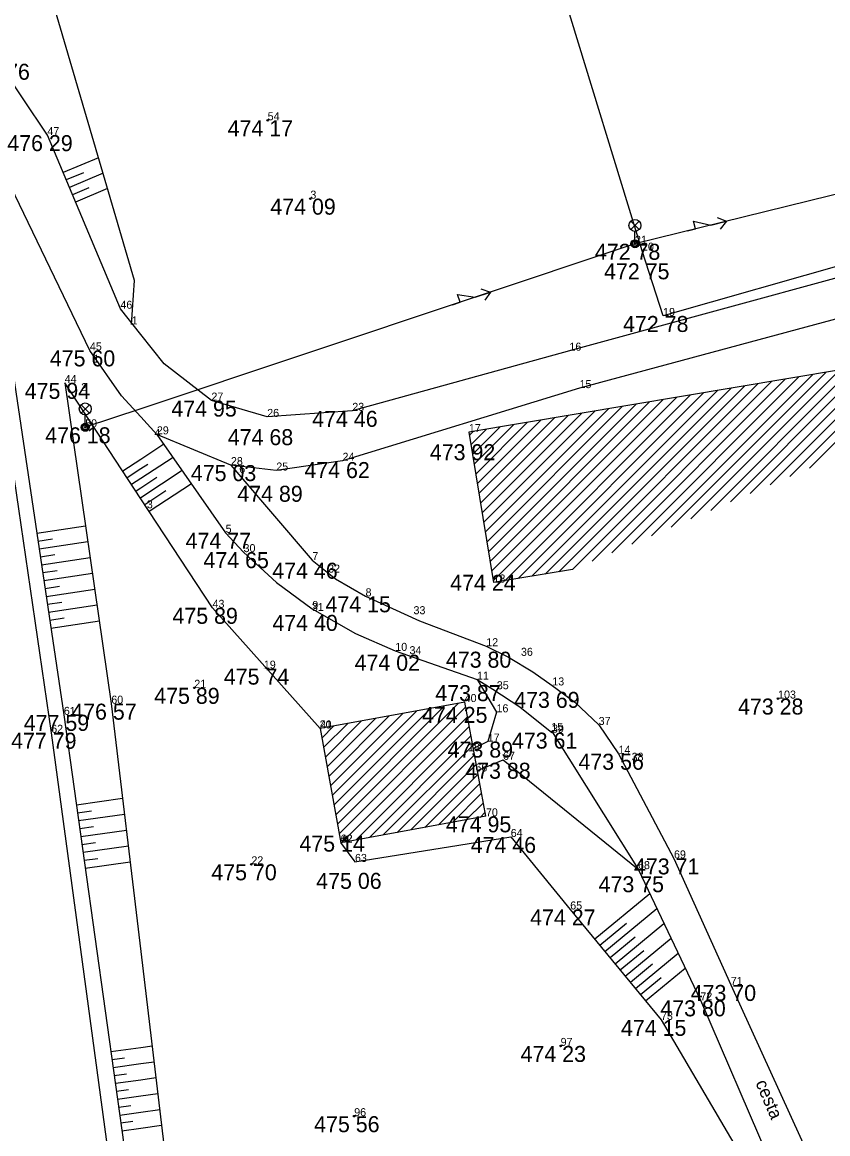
# Model space of a CAD drawing. Extents: x -559180 to -551373, y -1076947 to -1072071.
# Drawn here: x -553757.4 to -553707, y -1075865 to -1075795.6 of the extents above; entities that cross this region are included whole.
import ezdxf

# ---------------------------------------------------------------- set-up
doc = ezdxf.new("R2010")
doc.units = 0
for name, color, linetype in [('12_PLOTY', 7, 'Continuous'), ('14_BUDOVY', 7, 'Continuous'), ('17_KOMUNIKACE', 7, 'Continuous'), ('1_VODA_ZN', 7, 'Continuous'), ('20_EL_ZN', 7, 'Continuous'), ('26_SRAFY', 7, 'Continuous'), ('27_HRANA_PATA', 7, 'Continuous'), ('32', 7, 'Continuous'), ('3_BODY', 7, 'Continuous'), ('52_POPIS_UCELOVY', 7, 'Continuous'), ('6_VYSKY', 7, 'Continuous'), ('NNnadzemní', 7, 'Continuous')]:
    doc.layers.add(name, color=color, linetype=linetype)

# ---------------------------------------------------------------- blocks, each defined once
blk = doc.blocks.new('POINT_DISPLAY')
blk.add_line((0, 0), (0, 0))
blk = doc.blocks.new('SLB')
at = {"layer": '20_EL_ZN'}
for radius in [0.25, 0.158, 0.05]:
    blk.add_circle((0, 0), radius, dxfattribs=at)
blk = doc.blocks.new('LA')
at = {"layer": '20_EL_ZN'}
for p, q in [((-0.265, 1.415), (0.265, 0.885)), ((-0.265, 0.885), (0.265, 1.415)), ((0, 0), (0, 0.775))]:
    blk.add_line(p, q, dxfattribs=at)
for centre, radius in [((0, 1.15), 0.375), ((0, 0), 0.19), ((0, 0), 0.05)]:
    blk.add_circle(centre, radius, dxfattribs=at)
blk = doc.blocks.new('SLDP')
at = {"layer": '20_EL_ZN'}
for radius in [0.25, 0.158, 0.05]:
    blk.add_circle((0, 0), radius, dxfattribs=at)
blk = doc.blocks.new('T')
at = {"layer": '6_VYSKY'}
blk.add_circle((0, 0), 0.05, dxfattribs=at)
blk = doc.blocks.new('ELNN')
at = {"layer": '20_EL_ZN'}
for p, q in [((0, 0), (0.5, 0)), ((0.5, 0), (0.5, 0.5)), ((0.5, 0.5), (1.5, 0)), ((1.5, 0), (2.5, 0))]:
    blk.add_line(p, q, dxfattribs=at)
blk.add_lwpolyline([(2, 0.375), (2.5, 0), (2, -0.375)], dxfattribs=at)

msp = doc.modelspace()

# ---------------------------------------------------------------- linework, layer by layer
at = {"layer": '12_PLOTY'}
for p, q in [((-553718.66, -1075809.85), (-553725.883, -1075786.26)), ((-553717.34, -1075813.93), (-553718.66, -1075809.85)), ((-553703.74, -1075810.04), (-553717.34, -1075813.93))]:
    msp.add_line(p, q, dxfattribs=at)
at = {"layer": '14_BUDOVY'}
for p, q in [((-553706.13, -1075817.27), (-553729.49, -1075821.19)), ((-553729.49, -1075821.19), (-553727.95, -1075830.59)), ((-553723.016, -1075829.782), (-553727.95, -1075830.59)), ((-553729.75, -1075838.06), (-553738.79, -1075839.71)), ((-553728.42, -1075845.2), (-553729.75, -1075838.06)), ((-553738.79, -1075839.71), (-553737.5, -1075846.85)), ((-553728.42, -1075845.2), (-553737.5, -1075846.85))]:
    msp.add_line(p, q, dxfattribs=at)
at = {"layer": '17_KOMUNIKACE'}
for p, q in [((-553755.85, -1075802.63), (-553759.5, -1075797.19)), ((-553761.18, -1075801.95), (-553755.61, -1075839.98)), ((-553751.28, -1075813.48), (-553755.85, -1075802.63)), ((-553753.19, -1075816.08), (-553759.1, -1075803.86)), ((-553700, -1075809.79), (-553723.2, -1075816.1)), ((-553699.17, -1075812.14), (-553722.57, -1075818.44)), ((-553750, -1075815.096), (-553751.28, -1075813.48)), ((-553723.2, -1075816.1), (-553736.78, -1075819.86)), ((-553722.57, -1075818.44), (-553737.39, -1075822.98)), ((-553742.1, -1075820.24), (-553745.59, -1075819.22)), ((-553736.78, -1075819.86), (-553742.1, -1075820.24)), ((-553749, -1075821.33), (-553750, -1075820.236)), ((-553744.37, -1075823.25), (-553749, -1075821.33)), ((-553741.53, -1075823.59), (-553744.37, -1075823.25)), ((-553744.37, -1075823.25), (-553739.28, -1075829.19)), ((-553737.39, -1075822.98), (-553741.53, -1075823.59)), ((-553734.09, -1075834.86), (-553728.98, -1075836.66)), ((-553755.61, -1075839.98), (-553751.45, -1075870.69)), ((-553724.33, -1075839.86), (-553718.91, -1075848.5)), ((-553720.13, -1075841.29), (-553716.66, -1075847.83)), ((-553716.66, -1075847.83), (-553713.11, -1075855.74)), ((-553718.91, -1075848.5), (-553715.01, -1075856.7)), ((-553713.11, -1075855.74), (-553705.39, -1075872.58)), ((-553715.01, -1075856.7), (-553707.73, -1075873.54))]:
    msp.add_line(p, q, dxfattribs=at)
for points in [[(-553745.59, -1075819.22), (-553748.554, -1075816.921), (-553750, -1075815.096)], [(-553750, -1075820.236), (-553751.209, -1075818.914), (-553753.19, -1075816.08)], [(-553749, -1075821.33), (-553744.7, -1075827.48), (-553743.58, -1075828.69)], [(-553743.58, -1075828.69), (-553741.509, -1075830.583), (-553739.28, -1075832.24)], [(-553739.28, -1075829.19), (-553737.839, -1075830.365), (-553735.95, -1075831.45)], [(-553735.95, -1075831.45), (-553732.581, -1075832.974), (-553728.4, -1075834.57)], [(-553739.28, -1075832.24), (-553736.572, -1075833.772), (-553734.09, -1075834.86)], [(-553728.4, -1075834.57), (-553727.016, -1075835.244), (-553725.487, -1075836.162), (-553724.27, -1075837.02)], [(-553728.98, -1075836.66), (-553727.999, -1075837.255), (-553726.295, -1075838.348), (-553724.29, -1075839.97)], [(-553724.27, -1075837.02), (-553722.852, -1075838.074), (-553721.37, -1075839.49), (-553720.13, -1075841.29)]]:
    msp.add_lwpolyline(points, dxfattribs=at)
at = {"layer": '26_SRAFY'}
for p, q in [((-553752.653, -1075804.041), (-553754.864, -1075804.972)), ((-553753.59, -1075804.978), (-553754.67, -1075805.433)), ((-553752.369, -1075805.006), (-553754.475, -1075805.893)), ((-553753.255, -1075805.922), (-553754.281, -1075806.354)), ((-553752.086, -1075805.972), (-553754.087, -1075806.815)), ((-553748.565, -1075821.952), (-553750, -1075822.895)), ((-553750, -1075822.895), (-553751.128, -1075823.637)), ((-553747.992, -1075822.772), (-553750, -1075824.092)), ((-553749.566, -1075823.208), (-553750, -1075823.494)), ((-553750, -1075823.494), (-553750.853, -1075824.055)), ((-553750, -1075824.092), (-553750.579, -1075824.472)), ((-553747.418, -1075823.592), (-553750, -1075825.289)), ((-553749.004, -1075824.036), (-553750, -1075824.69)), ((-553750, -1075824.69), (-553750.304, -1075824.89)), ((-553746.845, -1075824.412), (-553749.48, -1075826.144)), ((-553750, -1075825.289), (-553750.029, -1075825.308)), ((-553748.443, -1075824.864), (-553749.755, -1075825.726)), ((-553753.46, -1075827.066), (-553756.51, -1075827.52)), ((-553755.522, -1075827.879), (-553756.436, -1075828.015)), ((-553753.316, -1075828.056), (-553756.362, -1075828.51)), ((-553755.375, -1075828.868), (-553756.289, -1075829.004)), ((-553753.173, -1075829.045), (-553756.215, -1075829.499)), ((-553755.229, -1075829.857), (-553756.141, -1075829.993)), ((-553753.029, -1075830.035), (-553756.068, -1075830.488)), ((-553755.083, -1075830.846), (-553755.994, -1075830.982)), ((-553752.886, -1075831.025), (-553755.92, -1075831.477)), ((-553754.937, -1075831.836), (-553755.847, -1075831.971)), ((-553752.742, -1075832.014), (-553755.773, -1075832.466)), ((-553754.79, -1075832.825), (-553755.699, -1075832.96)), ((-553752.598, -1075833.004), (-553755.625, -1075833.455)), ((-553751.141, -1075844.095), (-553754.032, -1075844.499)), ((-553753.098, -1075844.873), (-553753.962, -1075844.994)), ((-553751.022, -1075845.088), (-553753.893, -1075845.489)), ((-553752.966, -1075845.865), (-553753.824, -1075845.985)), ((-553750.904, -1075846.081), (-553753.755, -1075846.48)), ((-553752.833, -1075846.856), (-553753.685, -1075846.975)), ((-553750.785, -1075847.074), (-553753.616, -1075847.47)), ((-553752.701, -1075847.847), (-553753.547, -1075847.965)), ((-553750.667, -1075848.068), (-553753.478, -1075848.461)), ((-553718.171, -1075850.053), (-553721.614, -1075852.886)), ((-553717.729, -1075850.984), (-553720.978, -1075853.659)), ((-553719.623, -1075851.895), (-553721.296, -1075853.273)), ((-553717.286, -1075851.915), (-553720.342, -1075854.431)), ((-553719.084, -1075852.747), (-553720.66, -1075854.045)), ((-553716.843, -1075852.845), (-553719.707, -1075855.203)), ((-553718.545, -1075853.598), (-553720.025, -1075854.817)), ((-553716.401, -1075853.776), (-553719.071, -1075855.975)), ((-553718.006, -1075854.45), (-553719.389, -1075855.589)), ((-553717.466, -1075855.301), (-553718.754, -1075856.361)), ((-553715.958, -1075854.707), (-553718.436, -1075856.747)), ((-553750, -1075859.665), (-553751.875, -1075859.927)), ((-553749.294, -1075859.566), (-553750, -1075859.665)), ((-553751.034, -1075860.314), (-553751.806, -1075860.422)), ((-553750, -1075860.674), (-553751.736, -1075860.917)), ((-553749.175, -1075860.559), (-553750, -1075860.674)), ((-553750.902, -1075861.305), (-553751.667, -1075861.412)), ((-553749.057, -1075861.552), (-553750, -1075861.684)), ((-553750, -1075861.684), (-553751.598, -1075861.908)), ((-553750.769, -1075862.297), (-553751.529, -1075862.403)), ((-553750, -1075862.694), (-553751.459, -1075862.898)), ((-553748.938, -1075862.545), (-553750, -1075862.694)), ((-553750.637, -1075863.288), (-553751.39, -1075863.393)), ((-553750, -1075863.704), (-553751.321, -1075863.888)), ((-553748.82, -1075863.539), (-553750, -1075863.704)), ((-553750.504, -1075864.279), (-553751.252, -1075864.383)), ((-553750, -1075864.714), (-553751.182, -1075864.879)), ((-553748.701, -1075864.532), (-553750, -1075864.714))]:
    msp.add_line(p, q, dxfattribs=at)
at = {"layer": '27_HRANA_PATA'}
for p, q in [((-553750.4, -1075811.72), (-553755.78, -1075793.38)), ((-553759.66, -1075806.38), (-553754.82, -1075838.86)), ((-553750.58, -1075814.46), (-553750.4, -1075811.72)), ((-553750, -1075825.353), (-553754.76, -1075818.11)), ((-553754.76, -1075818.11), (-553751.85, -1075838.16)), ((-553745.52, -1075832.17), (-553750, -1075825.353)), ((-553738.79, -1075839.71), (-553745.52, -1075832.17)), ((-553728.98, -1075836.66), (-553727.76, -1075838.7)), ((-553751.85, -1075838.16), (-553750, -1075853.654)), ((-553727.76, -1075838.7), (-553728.31, -1075840.53)), ((-553754.82, -1075838.86), (-553750.5, -1075869.76)), ((-553728.31, -1075840.53), (-553729.208, -1075840.968)), ((-553728.952, -1075842.346), (-553727.35, -1075841.67)), ((-553727.35, -1075841.67), (-553718.91, -1075848.5)), ((-553737.51, -1075846.84), (-553736.61, -1075848.05)), ((-553736.61, -1075848.05), (-553726.87, -1075846.49)), ((-553726.87, -1075846.49), (-553723.15, -1075851.02)), ((-553723.15, -1075851.02), (-553717.47, -1075857.92)), ((-553750, -1075853.654), (-553748.25, -1075868.31)), ((-553717.47, -1075857.92), (-553708.16, -1075873.68))]:
    msp.add_line(p, q, dxfattribs=at)
at = {"layer": '32'}
for p, q in [((-553720.544, -1075828.724), (-553709.687, -1075817.867)), ((-553719.307, -1075828.195), (-553708.837, -1075817.724)), ((-553718.071, -1075827.666), (-553707.987, -1075817.582)), ((-553716.835, -1075827.137), (-553707.138, -1075817.439)), ((-553715.599, -1075826.608), (-553706.288, -1075817.296)), ((-553714.363, -1075826.078), (-553706.047, -1075817.763)), ((-553725.553, -1075830.197), (-553713.935, -1075818.58)), ((-553724.707, -1075830.059), (-553713.085, -1075818.437)), ((-553723.862, -1075829.92), (-553712.236, -1075818.295)), ((-553723.016, -1075829.782), (-553711.386, -1075818.152)), ((-553721.78, -1075829.253), (-553710.536, -1075818.009)), ((-553713.127, -1075825.549), (-553705.946, -1075818.369)), ((-553728.066, -1075829.882), (-553717.334, -1075819.15)), ((-553727.966, -1075830.49), (-553716.484, -1075819.008)), ((-553727.244, -1075830.474), (-553715.634, -1075818.865)), ((-553726.398, -1075830.336), (-553714.785, -1075818.722)), ((-553711.89, -1075825.02), (-553705.844, -1075818.974)), ((-553728.564, -1075826.844), (-553721.582, -1075819.863)), ((-553728.464, -1075827.452), (-553720.733, -1075819.72)), ((-553728.365, -1075828.06), (-553719.883, -1075819.578)), ((-553728.265, -1075828.667), (-553719.033, -1075819.435)), ((-553728.165, -1075829.275), (-553718.184, -1075819.293)), ((-553710.654, -1075824.491), (-553705.743, -1075819.58)), ((-553729.061, -1075823.807), (-553725.831, -1075820.576)), ((-553728.962, -1075824.414), (-553724.981, -1075820.433)), ((-553728.862, -1075825.022), (-553724.131, -1075820.291)), ((-553728.763, -1075825.629), (-553723.282, -1075820.148)), ((-553728.663, -1075826.237), (-553722.432, -1075820.006)), ((-553709.418, -1075823.962), (-553705.641, -1075820.185)), ((-553729.459, -1075821.376), (-553729.23, -1075821.146)), ((-553729.36, -1075821.984), (-553728.38, -1075821.004)), ((-553729.26, -1075822.591), (-553727.53, -1075820.861)), ((-553729.161, -1075823.199), (-553726.68, -1075820.719)), ((-553708.182, -1075823.433), (-553705.54, -1075820.791)), ((-553738.033, -1075843.902), (-553732.735, -1075838.605)), ((-553737.924, -1075844.501), (-553731.87, -1075838.447)), ((-553737.816, -1075845.1), (-553731.005, -1075838.289)), ((-553737.708, -1075845.699), (-553730.14, -1075838.131)), ((-553737.6, -1075846.298), (-553729.689, -1075838.387)), ((-553738.574, -1075840.908), (-553737.06, -1075839.394)), ((-553738.465, -1075841.507), (-553736.195, -1075839.236)), ((-553738.357, -1075842.106), (-553735.33, -1075839.078)), ((-553738.249, -1075842.705), (-553734.465, -1075838.921)), ((-553738.141, -1075843.303), (-553733.6, -1075838.763)), ((-553737.432, -1075846.838), (-553729.578, -1075838.983)), ((-553738.682, -1075840.309), (-553737.925, -1075839.552)), ((-553736.568, -1075846.681), (-553729.467, -1075839.579)), ((-553735.704, -1075846.524), (-553729.356, -1075840.175)), ((-553734.84, -1075846.367), (-553729.245, -1075840.772)), ((-553733.976, -1075846.21), (-553729.134, -1075841.368)), ((-553733.112, -1075846.053), (-553729.023, -1075841.964)), ((-553732.248, -1075845.896), (-553728.912, -1075842.56)), ((-553731.383, -1075845.739), (-553728.801, -1075843.156)), ((-553730.519, -1075845.581), (-553728.69, -1075843.752)), ((-553729.655, -1075845.424), (-553728.579, -1075844.348)), ((-553728.791, -1075845.267), (-553728.468, -1075844.944))]:
    msp.add_line(p, q, dxfattribs=at)
at = {"layer": 'NNnadzemní'}
for p, q in [((-553681.605, -1075800.205), (-553719.1, -1075809.42)), ((-553719.1, -1075809.42), (-553750, -1075819.729)), ((-553750, -1075819.729), (-553753.48, -1075820.89))]:
    msp.add_line(p, q, dxfattribs=at)

# ---------------------------------------------------------------- block references
at = {"layer": '1_VODA_ZN'}
for p in [(-553742.07, -1075801.7), (-553755.85, -1075802.63), (-553739.4, -1075806.6), (-553719.1, -1075809.42), (-553718.66, -1075809.85), (-553750.4, -1075811.72), (-553751.28, -1075813.48), (-553717.34, -1075813.93), (-553750.58, -1075814.46), (-553753.19, -1075816.08), (-553723.2, -1075816.1), (-553754.76, -1075818.11), (-553722.57, -1075818.44), (-553745.59, -1075819.22), (-553736.78, -1075819.86), (-553742.1, -1075820.24), (-553753.48, -1075820.89), (-553749, -1075821.33), (-553729.49, -1075821.19), (-553749.16, -1075821.49), (-553744.37, -1075823.25), (-553737.39, -1075822.98), (-553743.85, -1075823.74), (-553741.53, -1075823.59), (-553749.63, -1075825.95), (-553744.7, -1075827.48), (-553743.58, -1075828.69), (-553739.28, -1075829.19), (-553738.29, -1075829.97), (-553727.95, -1075830.59), (-553735.95, -1075831.45), (-553745.52, -1075832.17), (-553739.31, -1075832.37), (-553739.28, -1075832.24), (-553732.95, -1075832.57), (-553734.09, -1075834.86), (-553733.2, -1075835.07), (-553728.4, -1075834.57), (-553726.23, -1075835.17), (-553742.31, -1075835.97), (-553746.66, -1075837.17), (-553728.98, -1075836.66), (-553727.74, -1075837.26), (-553724.27, -1075837.02), (-553710.15, -1075837.84), (-553751.85, -1075838.16), (-553729.75, -1075838.06), (-553727.76, -1075838.7), (-553754.82, -1075838.86), (-553755.61, -1075839.98), (-553738.82, -1075839.71), (-553738.79, -1075839.71), (-553724.33, -1075839.86), (-553724.29, -1075839.97), (-553721.37, -1075839.49), (-553728.31, -1075840.53), (-553729.54, -1075841.13), (-553720.13, -1075841.29), (-553727.35, -1075841.67), (-553719.31, -1075841.73), (-553729.08, -1075842.4), (-553728.42, -1075845.2), (-553737.51, -1075846.84), (-553737.5, -1075846.85), (-553726.87, -1075846.49), (-553743.09, -1075848.2), (-553736.61, -1075848.05), (-553716.66, -1075847.83), (-553718.91, -1075848.5), (-553723.15, -1075851.02), (-553713.11, -1075855.74), (-553715.01, -1075856.7), (-553717.47, -1075857.92), (-553723.75, -1075859.55), (-553736.66, -1075863.94)]:
    msp.add_blockref('POINT_DISPLAY', p, dxfattribs=at)
at = {"layer": '20_EL_ZN'}
for name, p in [('LA', (-553719.1, -1075809.42)), ('SLDP', (-553719.1, -1075809.42)), ('LA', (-553753.48, -1075820.89)), ('SLB', (-553753.48, -1075820.89))]:
    msp.add_blockref(name, p, dxfattribs=at)
for p, xscale, yscale, rotation in [((-553715.807, -1075808.611), 0.999999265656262, 0.999999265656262, 13.80781763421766), ((-553730.512, -1075813.227), 1.000000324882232, 1.000000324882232, 18.45005123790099)]:
    msp.add_blockref('ELNN', p, dxfattribs=dict(at, xscale=xscale, yscale=yscale, rotation=rotation))
at = {"layer": '32'}
for p in [(-553723.016, -1075829.782), (-553738.79, -1075839.71)]:
    msp.add_blockref('POINT_DISPLAY', p, dxfattribs=at)
at = {"layer": '6_VYSKY'}
for p in [(-553742.07, -1075801.7), (-553742.07, -1075801.7), (-553739.4, -1075806.6), (-553739.4, -1075806.6), (-553746.66, -1075837.17), (-553746.66, -1075837.17), (-553710.15, -1075837.84), (-553710.15, -1075837.84), (-553743.09, -1075848.2), (-553743.09, -1075848.2), (-553723.75, -1075859.55), (-553723.75, -1075859.55), (-553736.66, -1075863.94), (-553736.66, -1075863.94)]:
    msp.add_blockref('T', p, dxfattribs=at)

# ---------------------------------------------------------------- texts
at = {"layer": '3_BODY'}
for s, p in [('54', (-553742.07, -1075801.7)), ('47', (-553755.85, -1075802.63)), ('3', (-553739.4, -1075806.6)), ('21', (-553719.1, -1075809.42)), ('20', (-553718.66, -1075809.85)), ('46', (-553751.28, -1075813.48)), ('19', (-553717.34, -1075813.93)), ('1', (-553750.58, -1075814.46)), ('45', (-553753.19, -1075816.08)), ('16', (-553723.2, -1075816.1)), ('1', (-553752.97, -1075816.85)), ('44', (-553754.76, -1075818.11)), ('2', (-553753.74, -1075818.63)), ('15', (-553722.57, -1075818.44)), ('27', (-553745.59, -1075819.22)), ('26', (-553742.1, -1075820.24)), ('23', (-553736.78, -1075819.86)), ('59', (-553753.48, -1075820.89)), ('4', (-553749.16, -1075821.49)), ('29', (-553749, -1075821.33)), ('17', (-553729.49, -1075821.19)), ('28', (-553744.37, -1075823.25)), ('24', (-553737.39, -1075822.98)), ('6', (-553743.85, -1075823.74)), ('25', (-553741.53, -1075823.59)), ('3', (-553749.63, -1075825.95)), ('5', (-553744.7, -1075827.48)), ('30', (-553743.58, -1075828.69)), ('7', (-553739.28, -1075829.19)), ('32', (-553738.29, -1075829.97)), ('18', (-553727.95, -1075830.59)), ('8', (-553735.95, -1075831.45)), ('43', (-553745.52, -1075832.17)), ('9', (-553739.28, -1075832.24)), ('31', (-553739.31, -1075832.37)), ('33', (-553732.95, -1075832.57)), ('10', (-553734.09, -1075834.86)), ('12', (-553728.4, -1075834.57)), ('34', (-553733.2, -1075835.07)), ('36', (-553726.23, -1075835.17)), ('19', (-553742.31, -1075835.97)), ('11', (-553728.98, -1075836.66)), ('13', (-553724.27, -1075837.02)), ('21', (-553746.66, -1075837.17)), ('35', (-553727.74, -1075837.26)), ('103', (-553710.15, -1075837.84)), ('60', (-553751.85, -1075838.16)), ('40', (-553729.75, -1075838.06)), ('61', (-553754.82, -1075838.86)), ('16', (-553727.76, -1075838.7)), ('20', (-553738.82, -1075839.71)), ('41', (-553738.79, -1075839.71)), ('15', (-553724.33, -1075839.86)), ('37', (-553721.37, -1075839.49)), ('62', (-553755.61, -1075839.98)), ('17', (-553728.31, -1075840.53)), ('39', (-553724.29, -1075839.97)), ('18', (-553729.54, -1075841.13)), ('14', (-553720.13, -1075841.29)), ('67', (-553727.35, -1075841.67)), ('38', (-553719.31, -1075841.73)), ('66', (-553729.08, -1075842.4)), ('70', (-553728.42, -1075845.2)), ('42', (-553737.5, -1075846.85)), ('62', (-553737.51, -1075846.84)), ('64', (-553726.87, -1075846.49)), ('22', (-553743.09, -1075848.2)), ('63', (-553736.61, -1075848.05)), ('69', (-553716.66, -1075847.83)), ('68', (-553718.91, -1075848.5)), ('65', (-553723.15, -1075851.02)), ('71', (-553713.11, -1075855.74)), ('72', (-553715.01, -1075856.7)), ('73', (-553717.47, -1075857.92)), ('97', (-553723.75, -1075859.55)), ('96', (-553736.66, -1075863.94))]:
    msp.add_text(s, height=0.5, dxfattribs=at).set_placement(p)
at = {"layer": '52_POPIS_UCELOVY'}
msp.add_text('cesta', height=0.8, rotation=293.37902, dxfattribs=at).set_placement((-553711.58, -1075861.863))
at = {"layer": '6_VYSKY'}
for s, p in [('476 76', (-553761.035, -1075799.17)), ('474 17', (-553744.575, -1075802.7)), ('476 29', (-553758.355, -1075803.63)), ('474 09', (-553741.905, -1075807.6)), ('472 78', (-553721.605, -1075810.42)), ('472 75', (-553721.033, -1075811.639)), ('472 78', (-553719.845, -1075814.93)), ('475 60', (-553755.695, -1075817.08)), ('475 94', (-553757.265, -1075819.11)), ('474 95', (-553748.095, -1075820.22)), ('474 46', (-553739.285, -1075820.86)), ('476 18', (-553755.985, -1075821.89)), ('474 68', (-553744.565, -1075822.005)), ('473 92', (-553731.929, -1075822.946)), ('475 03', (-553746.875, -1075824.25)), ('474 62', (-553739.774, -1075824.061)), ('474 89', (-553743.969, -1075825.543)), ('474 77', (-553747.205, -1075828.48)), ('474 65', (-553746.085, -1075829.69)), ('474 46', (-553741.785, -1075830.351)), ('474 24', (-553730.656, -1075831.107)), ('474 15', (-553738.455, -1075832.45)), ('475 89', (-553748.025, -1075833.17)), ('474 40', (-553741.775, -1075833.612)), ('474 02', (-553736.636, -1075836.102)), ('473 80', (-553730.925, -1075835.912)), ('475 74', (-553744.815, -1075836.97)), ('475 89', (-553749.165, -1075838.17)), ('473 87', (-553731.586, -1075838.002)), ('473 69', (-553726.654, -1075838.423)), ('473 28', (-553712.655, -1075838.84)), ('476 57', (-553754.355, -1075839.16)), ('474 25', (-553732.416, -1075839.362)), ('477 59', (-553757.325, -1075839.86)), ('477 79', (-553758.115, -1075840.98)), ('473 61', (-553726.795, -1075840.97)), ('473 89', (-553730.815, -1075841.53)), ('473 56', (-553722.635, -1075842.29)), ('473 88', (-553729.714, -1075842.851)), ('474 95', (-553730.925, -1075846.2)), ('475 14', (-553740.085, -1075847.407)), ('474 46', (-553729.375, -1075847.49)), ('475 70', (-553745.595, -1075849.2)), ('473 71', (-553719.165, -1075848.83)), ('475 06', (-553739.035, -1075849.735)), ('473 75', (-553721.375, -1075849.943)), ('474 27', (-553725.655, -1075852.02)), ('473 70', (-553715.615, -1075856.74)), ('473 80', (-553717.515, -1075857.7)), ('474 15', (-553719.975, -1075858.92)), ('474 23', (-553726.255, -1075860.55)), ('475 56', (-553739.165, -1075864.94))]:
    msp.add_text(s, height=1, dxfattribs=at).set_placement(p)

doc.saveas('drawing.dxf')
